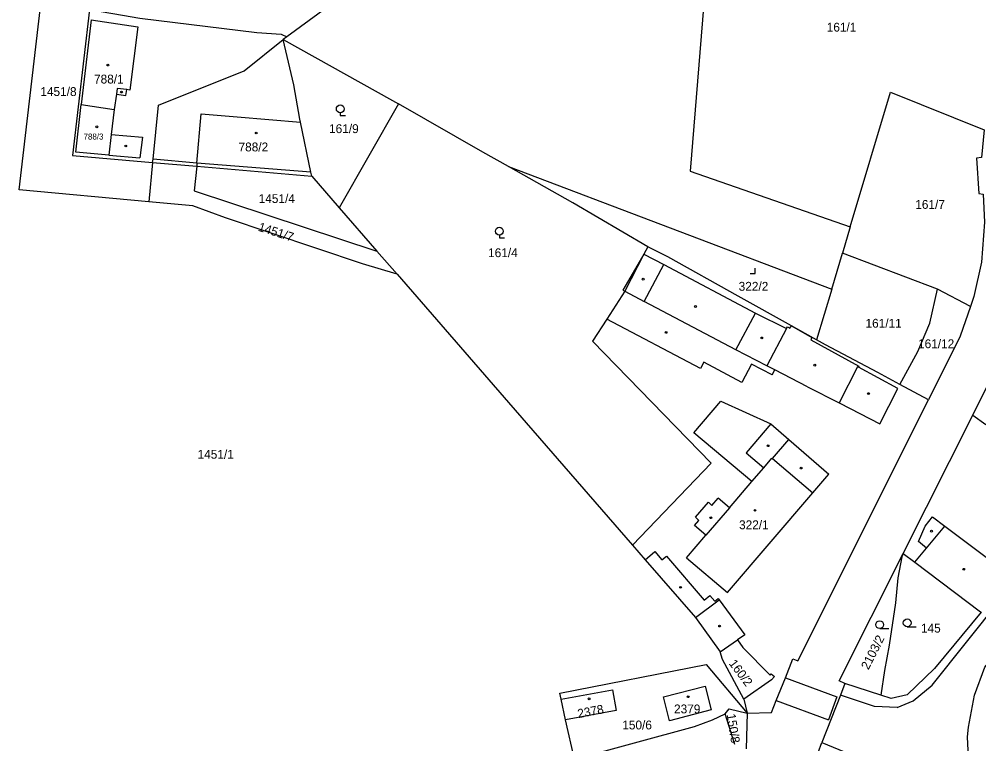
# Model space of a CAD drawing. Extents: x -679220 to -673243, y -1075091 to -1066557.
# Drawn here: x -676913.2 to -676729.1, y -1071369.7 to -1071230.6 of the extents above; entities that cross this region are included whole.
import ezdxf

# ---------------------------------------------------------------- set-up
doc = ezdxf.new("R2010")
doc.units = 0
for name, color, linetype in [('Hranice parcel', 7, 'Continuous'), ('Parcelní čísla', 7, 'Continuous'), ('Vnitřní kresba', 7, 'Continuous'), ('Značky budov', 7, 'Continuous'), ('Značky kultur', 7, 'Continuous')]:
    doc.layers.add(name, color=color, linetype=linetype)

msp = doc.modelspace()

# ---------------------------------------------------------------- linework, layer by layer
at = {"layer": 'Hranice parcel'}
for p, q in [((-676861.92, -1071233.98), (-676862.58, -1071234.47)), ((-676840.49, -1071246.81), (-676851.83, -1071266.81)), ((-676887.69, -1071258.07), (-676888.4, -1071265.64)), ((-676887.69, -1071258.07), (-676879.18, -1071258.8)), ((-676879.18, -1071258.8), (-676857.12, -1071260.7)), ((-676819.36, -1071258.86), (-676757.33, -1071282.38)), ((-676857.12, -1071260.7), (-676851.83, -1071266.81)), ((-676851.83, -1071266.81), (-676844.59, -1071275.11)), ((-676753.77, -1071270.45), (-676755.28, -1071275.51)), ((-676844.59, -1071275.11), (-676840.75, -1071279.54)), ((-676757.33, -1071282.38), (-676755.28, -1071275.51)), ((-676737.06, -1071282.38), (-676755.28, -1071275.51)), ((-676757.33, -1071282.38), (-676760.24, -1071292.13)), ((-676730.72, -1071285.73), (-676737.06, -1071282.38)), ((-676738.79, -1071303.66), (-676744.24, -1071300.7)), ((-676747.93, -1071360.35), (-676754.79, -1071358.12)), ((-676808.43, -1071365.09), (-676809.27, -1071361.13)), ((-676774.21, -1071361.1), (-676773.58, -1071363.79)), ((-676775.94, -1071369.83), (-676777.78, -1071363.89)), ((-676773.58, -1071363.79), (-676773.75, -1071370.63)), ((-676806.71, -1071372.6), (-676808.43, -1071365.09)), ((-676759.2, -1071369.45), (-676752.71, -1071372.09))]:
    msp.add_line(p, q, dxfattribs=at)
for points in [[(-676796.64, -1071197.95), (-676798.56, -1071198.62), (-676807.92, -1071201.15), (-676818.87, -1071205.44), (-676832.48, -1071212.49), (-676847.35, -1071223.29), (-676861.92, -1071233.98)], [(-676780.28, -1071207.89), (-676784.47, -1071259.78), (-676753.77, -1071270.45)], [(-676888.4, -1071265.64), (-676913.25, -1071263.32), (-676909.14, -1071228.22)], [(-676899.74, -1071228.73), (-676903.05, -1071256.75), (-676887.69, -1071258.07)], [(-676899.74, -1071228.73), (-676893.45, -1071229.78), (-676890.1, -1071230.37), (-676867.62, -1071233.15), (-676862.98, -1071233.44), (-676861.92, -1071233.98)], [(-676887.69, -1071258.07), (-676887.56, -1071257.48), (-676886.53, -1071247.08), (-676870.1, -1071240.47), (-676862.58, -1071234.47)], [(-676862.58, -1071234.47), (-676841.62, -1071246.16), (-676840.49, -1071246.81)], [(-676857.12, -1071260.7), (-676857.28, -1071259.97), (-676859.3, -1071250.33), (-676859.42, -1071249.78), (-676860.55, -1071243.16), (-676862.58, -1071234.47)], [(-676753.77, -1071270.45), (-676746.06, -1071244.57), (-676728.05, -1071251.79)], [(-676895.02, -1071247.91), (-676895.57, -1071252.71), (-676896.07, -1071256.68), (-676902.41, -1071256.11), (-676901.36, -1071246.96), (-676895.02, -1071247.91)], [(-676819.36, -1071258.86), (-676824.25, -1071256.1), (-676840.49, -1071246.81)], [(-676728.05, -1071251.79), (-676728.6, -1071257.13), (-676729.58, -1071257.28), (-676729.09, -1071264.03), (-676728.27, -1071264.14), (-676728.02, -1071269.56), (-676728.56, -1071277.24), (-676730.07, -1071283.83), (-676730.72, -1071285.73)], [(-676879.18, -1071258.8), (-676879.7, -1071263.54), (-676844.59, -1071275.11)], [(-676792.59, -1071274.31), (-676807, -1071265.83), (-676819.36, -1071258.86)], [(-676840.75, -1071279.54), (-676847.36, -1071277.56), (-676873.68, -1071268.71), (-676879.93, -1071266.43), (-676888.4, -1071265.64)], [(-676792.59, -1071274.31), (-676793.38, -1071275.68), (-676797.39, -1071282.6), (-676797.01, -1071282.8), (-676800.47, -1071288.15), (-676803.23, -1071292.41), (-676780.46, -1071315.83), (-676795.54, -1071331.55)], [(-676760.24, -1071292.13), (-676765.08, -1071289.42), (-676775.27, -1071283.75), (-676788.79, -1071276.18), (-676792.59, -1071274.31)], [(-676840.75, -1071279.54), (-676819.35, -1071304.16), (-676795.54, -1071331.55)], [(-676744.24, -1071300.7), (-676740.83, -1071294.34), (-676738.48, -1071288.94), (-676737.06, -1071282.38)], [(-676730.72, -1071285.73), (-676732.68, -1071291.45), (-676738.79, -1071303.66)], [(-676744.24, -1071300.7), (-676748.5, -1071298.39), (-676758.53, -1071293.09), (-676760.24, -1071292.13)], [(-676743.62, -1071333.13), (-676730.26, -1071306.58), (-676727.54, -1071301.18)], [(-676773.58, -1071363.79), (-676768.88, -1071363.68), (-676767.97, -1071361.37), (-676766.23, -1071356.99), (-676764.79, -1071353.35), (-676763.86, -1071353.72), (-676738.79, -1071303.66)], [(-676795.54, -1071331.55), (-676793.12, -1071334.33), (-676783.46, -1071345.44), (-676778.77, -1071352)], [(-676754.79, -1071358.12), (-676755.93, -1071357.59), (-676743.62, -1071333.13)], [(-676743.62, -1071333.13), (-676743.88, -1071333.79), (-676744.66, -1071337.81), (-676745.09, -1071342.61), (-676746.28, -1071350.73), (-676747.18, -1071355.63), (-676747.93, -1071360.35)], [(-676743.62, -1071333.13), (-676741.37, -1071334.83), (-676728.81, -1071344.34), (-676728.66, -1071344.41)], [(-676711.15, -1071388.7), (-676720.68, -1071385.54), (-676730.79, -1071373.44), (-676731.13, -1071370.95), (-676731.25, -1071368.33), (-676731.11, -1071366.47), (-676729.91, -1071360.31), (-676727.92, -1071354.93), (-676716.83, -1071341.33)], [(-676728.66, -1071344.41), (-676737.62, -1071355.23), (-676742.85, -1071360.26), (-676745.95, -1071361), (-676747.93, -1071360.35)], [(-676778.77, -1071352), (-676775.44, -1071349.7), (-676774.4, -1071351.19), (-676769.17, -1071356.5), (-676768.96, -1071356.25), (-676768.32, -1071356.73), (-676768.86, -1071357.37), (-676774.21, -1071361.1)], [(-676774.21, -1071361.1), (-676778.27, -1071353.52), (-676778.77, -1071352)], [(-676809.27, -1071361.13), (-676809.53, -1071359.92), (-676781.44, -1071354.42), (-676773.58, -1071363.79)], [(-676754.79, -1071358.12), (-676755.66, -1071360.35), (-676759.2, -1071369.45)], [(-676809.27, -1071361.13), (-676799.4, -1071359.28), (-676798.7, -1071363.27), (-676808.43, -1071365.09)], [(-676789.64, -1071360.64), (-676781.62, -1071358.58), (-676780.44, -1071363.17), (-676788.46, -1071365.23), (-676789.64, -1071360.64)], [(-676806.71, -1071372.6), (-676783.69, -1071366.35), (-676780.19, -1071365.08), (-676777.78, -1071363.89)], [(-676777.78, -1071363.89), (-676776.98, -1071362.98), (-676773.58, -1071363.79)], [(-676760.97, -1071411.13), (-676762.45, -1071400.11), (-676763.03, -1071395.88), (-676762.98, -1071384.79), (-676759.94, -1071371.35), (-676759.2, -1071369.45)]]:
    msp.add_lwpolyline(points, dxfattribs=at)
at = {"layer": 'Vnitřní kresba'}
for p, q in [((-676899.46, -1071230.69), (-676901.36, -1071246.96)), ((-676899.46, -1071230.69), (-676890.49, -1071232.02)), ((-676890.49, -1071232.02), (-676892.02, -1071244.18)), ((-676894.46, -1071243.87), (-676894.6, -1071244.98)), ((-676892.62, -1071244.1), (-676894.46, -1071243.87)), ((-676892.76, -1071245.21), (-676892.62, -1071244.1)), ((-676892.02, -1071244.18), (-676892.62, -1071244.1)), ((-676894.6, -1071244.98), (-676895.02, -1071247.91)), ((-676894.6, -1071244.98), (-676892.76, -1071245.21)), ((-676879.13, -1071258.19), (-676878.3, -1071248.73)), ((-676878.3, -1071248.73), (-676871.4, -1071249.31)), ((-676871.4, -1071249.31), (-676859.3, -1071250.33)), ((-676895.57, -1071252.71), (-676889.59, -1071253.25)), ((-676889.59, -1071253.25), (-676890.13, -1071257.21)), ((-676896.07, -1071256.68), (-676890.13, -1071257.21)), ((-676879.13, -1071258.19), (-676887.56, -1071257.48)), ((-676879.13, -1071258.19), (-676879.18, -1071258.8)), ((-676857.28, -1071259.97), (-676879.13, -1071258.19)), ((-676793.38, -1071275.68), (-676797.01, -1071282.8)), ((-676793.38, -1071275.68), (-676789.58, -1071277.69)), ((-676793.29, -1071284.77), (-676789.58, -1071277.69)), ((-676789.58, -1071277.69), (-676771.96, -1071287)), ((-676797.01, -1071282.8), (-676793.29, -1071284.77)), ((-676775.75, -1071294.07), (-676793.29, -1071284.77)), ((-676782.52, -1071297.62), (-676800.47, -1071288.15)), ((-676775.75, -1071294.07), (-676771.96, -1071287)), ((-676771.96, -1071287), (-676765.99, -1071289.97)), ((-676765.99, -1071289.97), (-676769.8, -1071297.11)), ((-676765.99, -1071289.97), (-676765.83, -1071289.66)), ((-676765.83, -1071289.66), (-676765.34, -1071289.91)), ((-676765.34, -1071289.91), (-676765.08, -1071289.42)), ((-676765.08, -1071289.42), (-676761.13, -1071291.71)), ((-676761.13, -1071291.71), (-676761.35, -1071292.1)), ((-676761.35, -1071292.1), (-676752.1, -1071297.18)), ((-676769.8, -1071297.11), (-676775.75, -1071294.07)), ((-676781.89, -1071296.43), (-676782.52, -1071297.62)), ((-676774.56, -1071300.29), (-676781.89, -1071296.43)), ((-676772.72, -1071296.79), (-676774.56, -1071300.29)), ((-676768.78, -1071298.86), (-676772.72, -1071296.79)), ((-676768.27, -1071297.89), (-676769.8, -1071297.11)), ((-676752.4, -1071297.31), (-676755.89, -1071304.23)), ((-676752.22, -1071297.4), (-676752.4, -1071297.31)), ((-676752.1, -1071297.18), (-676752.22, -1071297.4)), ((-676744.63, -1071301.44), (-676752.22, -1071297.4)), ((-676768.78, -1071298.86), (-676768.27, -1071297.89)), ((-676761.98, -1071301.12), (-676768.27, -1071297.89)), ((-676761.98, -1071301.12), (-676755.89, -1071304.23)), ((-676748.12, -1071308.24), (-676744.63, -1071301.44)), ((-676783.76, -1071309.95), (-676778.61, -1071303.93)), ((-676778.61, -1071303.93), (-676769.04, -1071308.25)), ((-676755.89, -1071304.23), (-676755.76, -1071304.3)), ((-676755.76, -1071304.3), (-676748.12, -1071308.24)), ((-676730.26, -1071306.58), (-676727.75, -1071308.39)), ((-676769.04, -1071308.25), (-676773.76, -1071313.84)), ((-676769.04, -1071308.25), (-676765.59, -1071311.27)), ((-676772.65, -1071319.31), (-676783.76, -1071309.95)), ((-676768.69, -1071314.92), (-676765.59, -1071311.27)), ((-676765.59, -1071311.27), (-676757.89, -1071317.92)), ((-676738.05, -1071358.42), (-676700.61, -1071311.38)), ((-676773.76, -1071313.84), (-676770.39, -1071316.68)), ((-676770.39, -1071316.68), (-676768.81, -1071314.82)), ((-676768.81, -1071314.82), (-676768.69, -1071314.92)), ((-676768.69, -1071314.92), (-676760.96, -1071321.51)), ((-676772.65, -1071319.31), (-676770.39, -1071316.68)), ((-676760.96, -1071321.51), (-676757.89, -1071317.92)), ((-676776.96, -1071324.38), (-676772.65, -1071319.31)), ((-676777.3, -1071340.62), (-676760.96, -1071321.51)), ((-676783.48, -1071326.2), (-676781, -1071323.32)), ((-676781, -1071323.32), (-676780.32, -1071323.9)), ((-676780.32, -1071323.9), (-676779.13, -1071322.51)), ((-676776.96, -1071324.38), (-676779.13, -1071322.51)), ((-676776.96, -1071324.38), (-676781.47, -1071329.62)), ((-676783.64, -1071327.75), (-676782.8, -1071326.78)), ((-676782.8, -1071326.78), (-676783.48, -1071326.2)), ((-676739.39, -1071327.92), (-676738, -1071326.08)), ((-676738, -1071326.08), (-676735.6, -1071327.89)), ((-676781.47, -1071329.62), (-676783.64, -1071327.75)), ((-676740.67, -1071330.85), (-676739.39, -1071327.92)), ((-676739.13, -1071332.13), (-676735.6, -1071327.89)), ((-676735.6, -1071327.89), (-676723.09, -1071337.33)), ((-676785.19, -1071333.98), (-676781.47, -1071329.62)), ((-676739.13, -1071332.13), (-676740.67, -1071330.85)), ((-676793.12, -1071334.33), (-676791.28, -1071332.76)), ((-676791.28, -1071332.76), (-676789.9, -1071334.37)), ((-676741.37, -1071334.83), (-676739.13, -1071332.13)), ((-676789.9, -1071334.37), (-676789.06, -1071333.65)), ((-676789.06, -1071333.65), (-676781.8, -1071342.13)), ((-676785.19, -1071333.98), (-676777.3, -1071340.62)), ((-676781.8, -1071342.13), (-676780.69, -1071341.18)), ((-676780.69, -1071341.18), (-676779.73, -1071342.3)), ((-676779.73, -1071342.3), (-676779.12, -1071341.77)), ((-676779.12, -1071341.77), (-676778.92, -1071342.04)), ((-676783.46, -1071345.44), (-676778.92, -1071342.04)), ((-676778.92, -1071342.04), (-676774.03, -1071348.73)), ((-676774.03, -1071348.73), (-676775.44, -1071349.7)), ((-676766.23, -1071356.99), (-676756.33, -1071360.63)), ((-676741.73, -1071361.45), (-676738.05, -1071358.42)), ((-676749.11, -1071362.52), (-676755.66, -1071360.35)), ((-676767.97, -1071361.37), (-676757.96, -1071365.05)), ((-676756.33, -1071360.63), (-676757.96, -1071365.05)), ((-676744.76, -1071362.69), (-676741.73, -1071361.45)), ((-676744.76, -1071362.69), (-676749.11, -1071362.52))]:
    msp.add_line(p, q, dxfattribs=at)
at = {"layer": 'Značky budov'}
for centre in [(-676896.23, -1071239.39), (-676893.61, -1071244.57), (-676898.34, -1071251.24), (-676867.75, -1071252.43), (-676892.81, -1071254.92), (-676793.5, -1071280.47), (-676783.47, -1071285.73), (-676789.12, -1071290.7), (-676770.77, -1071291.77), (-676760.6, -1071296.98), (-676750.28, -1071302.45), (-676769.55, -1071312.45), (-676763.22, -1071316.74), (-676772.05, -1071324.86), (-676780.54, -1071326.28), (-676738.19, -1071328.87), (-676732, -1071336.17), (-676786.33, -1071339.64), (-676778.84, -1071347.07), (-676803.9, -1071361.05), (-676784.89, -1071360.64)]:
    msp.add_circle(centre, 0.175, dxfattribs=at)
at = {"layer": 'Značky kultur'}
for p, q in [((-676851.64, -1071248.55), (-676851.64, -1071249.05)), ((-676851.64, -1071249.05), (-676850.64, -1071249.05)), ((-676821.11, -1071272.03), (-676821.11, -1071272.53)), ((-676821.11, -1071272.53), (-676820.11, -1071272.53)), ((-676772, -1071279.39), (-676772, -1071278.39)), ((-676773, -1071279.39), (-676772, -1071279.39)), ((-676742.85, -1071347.21), (-676741.1, -1071347.21)), ((-676748.13, -1071347.56), (-676746.38, -1071347.56))]:
    msp.add_line(p, q, dxfattribs=at)
for centre in [(-676851.64, -1071247.8), (-676821.11, -1071271.28), (-676748.13, -1071346.81), (-676742.85, -1071346.46)]:
    msp.add_circle(centre, 0.75, dxfattribs=at)

# ---------------------------------------------------------------- texts
at = {"layer": 'Parcelní čísla'}
for s, height, p in [('161/1', 1.7, (-676758.29, -1071232.97)), ('788/1', 1.7, (-676898.89, -1071242.93)), ('1451/8', 1.7, (-676909.19, -1071245.33)), ('161/9', 1.7, (-676853.79, -1071252.45)), ('788/3', 1.14, (-676900.9, -1071253.68)), ('788/2', 1.7, (-676871.16, -1071255.96)), ('1451/4', 1.7, (-676867.3, -1071265.87)), ('161/7', 1.7, (-676741.3, -1071266.99)), ('161/4', 1.7, (-676823.27, -1071276.26)), ('322/2', 1.7, (-676775.19, -1071282.71)), ('161/11', 1.7, (-676750.85, -1071289.8)), ('161/12', 1.7, (-676740.77, -1071293.73)), ('1451/1', 1.7, (-676879.02, -1071314.95)), ('322/1', 1.7, (-676775.11, -1071328.48)), ('145', 1.7, (-676740.21, -1071348.32)), ('2379', 1.7, (-676787.59, -1071363.83)), ('150/6', 1.7, (-676797.52, -1071366.91))]:
    msp.add_text(s, height=height, dxfattribs=at).set_placement(p)
for s, rotation, p in [('1451/7', 342, (-676867.52, -1071271.15)), ('2103/2', 63, (-676750.29, -1071355.57)), ('160/2', 307, (-676777.16, -1071354.27)), ('2378', 11, (-676805.94, -1071364.75)), ('150/8', 279, (-676777.49, -1071364.03))]:
    msp.add_text(s, height=1.7, rotation=rotation, dxfattribs=at).set_placement(p)

doc.saveas('drawing.dxf')
